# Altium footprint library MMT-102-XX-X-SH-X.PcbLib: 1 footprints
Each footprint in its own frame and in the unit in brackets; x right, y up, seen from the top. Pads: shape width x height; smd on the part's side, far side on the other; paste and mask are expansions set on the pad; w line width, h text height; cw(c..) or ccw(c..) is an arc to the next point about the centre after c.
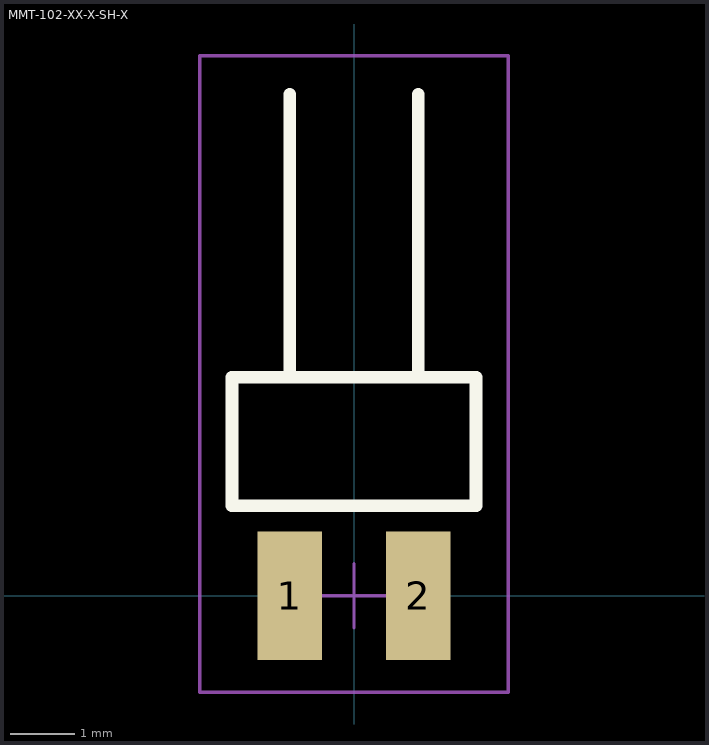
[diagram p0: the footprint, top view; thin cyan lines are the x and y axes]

## MMT-102-XX-X-SH-X [mm] "2.00mm pitch, 2 pin, header; single row"
height 2
pads (2):
  rect 1x2 smd mask+0: 1(-1,0) 2(1,0)
Top Overlay:
  lines w0.2: -1,3.4 -1,7.8 ; 1,3.4 1,7.8 ; -1.9,1.4 -1.9,3.4 1.9,3.4 1.9,1.4 -1.9,1.4
Mechanical 12:
  lines w0.001: -1.9,1.4 -1.9,3.4 1.9,3.4 1.9,1.4 -1.9,1.4
Mechanical 13:
  lines w0.1: -1,3.4 -1,7.8 ; 1,3.4 1,7.8 ; -1.9,1.4 -1.9,3.4 1.9,3.4 1.9,1.4 -1.9,1.4
  text ".Designator" at 0.254,0.254 h1.52
Mechanical 15:
  lines w0.05: -0.5,0 0.5,0 ; 0,-0.5 0,0.5 ; -2.4,-1.5 -2.4,8.4 2.4,8.4 2.4,-1.5 -2.4,-1.5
